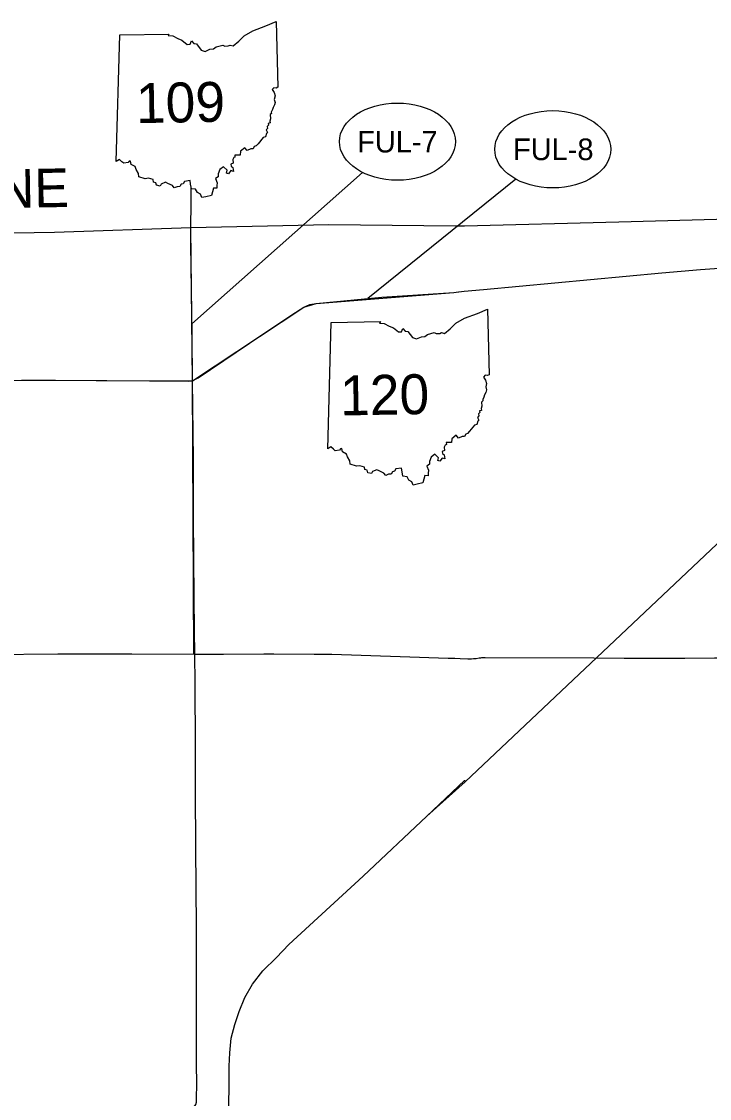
# Model space of a CAD drawing. Extents: x 0 to 849, y 0 to 440.
# Drawn here: x 399.3 to 488.2, y 214.9 to 354.2 of the extents above; entities that cross this region are included whole.
import ezdxf

# ---------------------------------------------------------------- set-up
doc = ezdxf.new("R2010")
doc.units = 0
for name, color, linetype in [('GM_X_Adjacent_County_Text', 7, 'Continuous'), ('GM_X_County', 7, 'Continuous'), ('GM_X_Interstate_Route', 7, 'Continuous'), ('PV_P_Walk', 7, 'Continuous'), ('RD_X_RR_2', 7, 'Continuous'), ('SH_Data', 7, 'Continuous')]:
    doc.layers.add(name, color=color, linetype=linetype)

msp = doc.modelspace()

# ---------------------------------------------------------------- linework, layer by layer
at = {"layer": 'GM_X_County'}
msp.add_lwpolyline([(390.27, 326.72), (403.53, 326.93), (421.18, 327.57), (438.99, 327.93), (455.38, 327.76), (456.49, 327.78), (456.55, 327.79), (476.51, 328.3), (493.89, 328.75), (511.84, 329.22), (529.24, 329.42), (538.61, 329.77), (546.79, 330.09), (564.28, 330.05), (564.46, 320.49), (564.74, 306.39), (564.89, 288.89), (565.03, 271.67), (565.17, 254.2), (565.19, 237.05), (565.2, 232.33), (565.21, 219.21), (565.34, 205.31)], dxfattribs=at)
at = {"layer": 'GM_X_Interstate_Route'}
for points in [[(421.67, 272.36), (421.64, 275.45), (421.61, 279.68), (421.51, 290.02), (421.49, 297.56), (421.36, 307.71), (421.35, 313.63), (421.17, 325.41), (421.22, 332.88)], [(458.99, 319.55), (482.08, 321.71), (487.07, 322.14), (491.86, 322.48), (493.95, 322.64), (496.53, 322.83), (502.87, 323.38), (507.37, 323.78), (509.49, 323.99), (509.55, 323.89), (509.68, 323.81), (510, 323.78), (510.29, 323.79)], [(421.36, 307.71), (421.86, 307.97), (422.13, 308.11), (428.77, 312.61), (434.21, 316.25), (435.77, 317.25), (436.54, 317.59), (437.37, 317.71), (439, 317.86), (455.18, 319.16), (455.79, 319.24), (455.8, 319.24)], [(455.8, 319.24), (456.5, 319.33), (458.99, 319.55)], [(392.29, 307.71), (392.29, 307.71), (394.11, 307.73), (395.71, 307.75), (395.96, 307.75), (399.29, 307.79), (399.29, 307.79)], [(399.29, 307.79), (400.51, 307.81)], [(400.51, 307.81), (400.86, 307.81), (403.66, 307.8), (408.93, 307.77), (415.82, 307.73), (420.8, 307.67), (421.36, 307.71)], [(326.28, 272.09), (332.98, 272.15), (340.32, 272.06), (344.27, 272.15), (346.61, 272.16), (351.08, 272.15), (358.34, 272.18), (366.67, 272.21), (368.5, 272.22), (377.41, 272.27), (385.4, 272.28), (390.75, 272.3), (391.52, 272.3), (395.11, 272.33), (403.95, 272.4), (411.47, 272.38), (412.84, 272.38), (413.53, 272.38)], [(413.53, 272.38), (421.67, 272.36)], [(421.67, 272.36), (425.4, 272.37), (430.59, 272.38), (431.9, 272.39), (437.13, 272.37), (439.41, 272.36), (448.21, 272.07), (454.45, 271.85), (454.56, 271.84)], [(421.89, 219.36), (421.9, 226.87), (421.89, 237.03), (421.83, 247.32), (421.76, 254.67), (421.75, 260.41), (421.71, 268.55), (421.67, 272.36)], [(454.56, 271.84), (455.28, 271.82), (455.97, 271.79), (456.98, 271.76), (457.04, 271.76), (457.46, 271.75), (457.72, 271.79), (457.99, 271.81)], [(457.99, 271.81), (458.07, 271.81), (458.45, 271.88), (458.66, 271.9), (458.81, 271.91), (459.24, 271.93), (473.29, 271.88)], [(473.29, 271.88), (477.19, 271.85), (485.05, 271.86), (488.86, 271.88), (490.09, 271.89), (493.69, 271.94), (498.86, 271.92), (498.96, 271.92), (504.03, 272.04), (507.8, 272.16), (507.87, 272.16), (510.81, 272.18), (511.47, 272.28), (512.4, 272.32), (516.54, 272.25), (518.32, 272.23), (523.68, 272.16), (527.6, 272.15), (528.32, 272.14)], [(419.15, 207.4), (419.18, 210.2), (419.2, 210.64), (419.29, 211.02), (419.53, 211.37), (421.58, 213.8), (421.8, 214.1), (421.91, 214.4), (421.9, 214.92), (421.92, 216.72), (421.89, 219.36)]]:
    msp.add_lwpolyline(points, dxfattribs=at)
at = {"layer": 'PV_P_Walk'}
for p, q in [((411.53, 336.1), (411.99, 352.48)), ((411.53, 336.1), (411.99, 352.48)), ((438.86, 298.91), (439.32, 315.28))]:
    msp.add_line(p, q, dxfattribs=at)
for points in [[(411.99, 352.48), (418.34, 352.58), (418.24, 352.39), (418.84, 352.34), (419.48, 351.99), (420.02, 351.77), (420.68, 351.25), (421.07, 351.26), (421.24, 351.69), (421.54, 351.36), (421.9, 351.3), (422.52, 350.51), (423.03, 350.34), (423.64, 350.61), (424.1, 350.66), (424.43, 350.92), (425.3, 351.15), (425.55, 351.01), (426.01, 351.04), (426.24, 351.14), (426.64, 351.05), (427.35, 351.65), (428.08, 352.35), (429.2, 353.01), (430.88, 353.64), (432.21, 354.2), (432.4, 345.7)], [(411.99, 352.48), (418.34, 352.58), (418.24, 352.39), (418.84, 352.34), (419.48, 351.99), (420.02, 351.77), (420.68, 351.25), (421.07, 351.26), (421.24, 351.69), (421.54, 351.36), (421.9, 351.3), (422.52, 350.51), (423.03, 350.34), (423.64, 350.61), (424.1, 350.66), (424.43, 350.92), (425.3, 351.15), (425.55, 351.01), (426.01, 351.04), (426.24, 351.14), (426.64, 351.05), (427.35, 351.65), (428.08, 352.35), (429.2, 353.01), (430.88, 353.64), (432.21, 354.2), (432.4, 345.7)], [(432.4, 345.7), (432.2, 345.58), (431.9, 345.64), (431.69, 345.4), (431.95, 345), (432.06, 344.58), (431.96, 344.12), (432.06, 343.74), (431.99, 343.42), (431.8, 343.1), (431.73, 342.8), (431.57, 342.48), (431.59, 342.3), (431.43, 342.16), (431.46, 341.63), (431.38, 341.33), (431.41, 341.08), (431.16, 341.01), (431.21, 340.8), (431.05, 340.64), (431.09, 340.36), (430.91, 340.18), (431.08, 339.83), (430.94, 339.71), (430.82, 339.28), (430.5, 339.19), (429.85, 338.4), (429.63, 338.1), (429.37, 338.02), (429.23, 337.72), (428.91, 337.72), (428.44, 337.5), (428.13, 337.87), (427.59, 337.43), (427.53, 336.92), (426.84, 336.93), (426.87, 336.67), (426.72, 336.6), (426.58, 336.34), (426.66, 335.88), (426.34, 335.76), (426.38, 335.5), (426.58, 335.33), (426.67, 334.82), (426.33, 334.93), (426.05, 334.5), (425.77, 334.6), (425.86, 334.96), (425.38, 335.4), (424.92, 335.05), (424.68, 334.49), (424.68, 334.11), (424.34, 333.89), (424.56, 333.35), (424.52, 332.99), (424.52, 332.64), (424.1, 332.65), (423.84, 331.71)], [(432.4, 345.7), (432.2, 345.58), (431.9, 345.64), (431.69, 345.4), (431.95, 345), (432.06, 344.58), (431.96, 344.12), (432.06, 343.74), (431.99, 343.42), (431.8, 343.1), (431.73, 342.8), (431.57, 342.48), (431.59, 342.3), (431.43, 342.16), (431.46, 341.63), (431.38, 341.33), (431.41, 341.08), (431.16, 341.01), (431.21, 340.8), (431.05, 340.64), (431.09, 340.36), (430.91, 340.18), (431.08, 339.83), (430.94, 339.71), (430.82, 339.28), (430.5, 339.19), (429.85, 338.4), (429.63, 338.1), (429.37, 338.02), (429.23, 337.72), (428.91, 337.72), (428.44, 337.5), (428.13, 337.87), (427.59, 337.43), (427.53, 336.92), (426.84, 336.93), (426.87, 336.67), (426.72, 336.6), (426.58, 336.34), (426.66, 335.88), (426.34, 335.76), (426.38, 335.5), (426.58, 335.33), (426.67, 334.82), (426.33, 334.93), (426.05, 334.5), (425.77, 334.6), (425.86, 334.96), (425.38, 335.4), (424.92, 335.05), (424.68, 334.49), (424.68, 334.11), (424.34, 333.89), (424.56, 333.35), (424.52, 332.99), (424.52, 332.64), (424.1, 332.65), (423.84, 331.71)], [(423.84, 331.71), (423.1, 331.53), (422.58, 331.42), (422.4, 331.85), (422.03, 332.07), (421.79, 332.5), (421.26, 332.56), (421.14, 333.15), (421.08, 333.63), (420.36, 333.51), (420.16, 333.22), (419.9, 333.14), (419.75, 332.85), (419.4, 332.82), (419.03, 332.68), (418.78, 332.97), (418.17, 333.26), (417.89, 333.41), (417.32, 333.18), (417.19, 332.91), (416.73, 333.03), (416.63, 333.33), (416.35, 333.43), (416.29, 333.75), (415.69, 333.93), (415.24, 333.86), (414.44, 334.12), (414.39, 334.55), (414.11, 335.07), (413.97, 335.43), (413.46, 335.71), (413.36, 336.14), (413.2, 336.13), (413.05, 335.96), (412.49, 335.88), (412.26, 336.05), (411.95, 336.35), (411.53, 336.1)], [(423.84, 331.71), (423.1, 331.53), (422.58, 331.42), (422.4, 331.85), (422.03, 332.07), (421.79, 332.5), (421.26, 332.56), (421.14, 333.15), (421.08, 333.63), (420.36, 333.51), (420.16, 333.22), (419.9, 333.14), (419.75, 332.85), (419.4, 332.82), (419.03, 332.68), (418.78, 332.97), (418.17, 333.26), (417.89, 333.41), (417.32, 333.18), (417.19, 332.91), (416.73, 333.03), (416.63, 333.33), (416.35, 333.43), (416.29, 333.75), (415.69, 333.93), (415.24, 333.86), (414.44, 334.12), (414.39, 334.55), (414.11, 335.07), (413.97, 335.43), (413.46, 335.71), (413.36, 336.14), (413.2, 336.13), (413.05, 335.96), (412.49, 335.88), (412.26, 336.05), (411.95, 336.35), (411.53, 336.1)], [(439.32, 315.28), (445.67, 315.39), (445.57, 315.19), (446.17, 315.15), (446.81, 314.8), (447.35, 314.58), (448, 314.06), (448.4, 314.07), (448.56, 314.49), (448.87, 314.16), (449.22, 314.1), (449.84, 313.32), (450.36, 313.15), (450.97, 313.42), (451.43, 313.46), (451.76, 313.73), (452.63, 313.96), (452.87, 313.82), (453.34, 313.85), (453.57, 313.95), (453.97, 313.86), (454.68, 314.45), (455.41, 315.16), (456.53, 315.82), (458.21, 316.45), (459.53, 317.01), (459.72, 308.51)], [(459.72, 308.51), (459.53, 308.39), (459.22, 308.45), (459.02, 308.21), (459.27, 307.81), (459.39, 307.39), (459.29, 306.93), (459.39, 306.55), (459.32, 306.23), (459.13, 305.91), (459.06, 305.6), (458.9, 305.29), (458.91, 305.11), (458.76, 304.97), (458.79, 304.43), (458.71, 304.14), (458.73, 303.89), (458.48, 303.82), (458.54, 303.61), (458.38, 303.45), (458.41, 303.17), (458.23, 302.99), (458.41, 302.63), (458.27, 302.52), (458.15, 302.09), (457.83, 302), (457.18, 301.21), (456.95, 300.91), (456.7, 300.83), (456.56, 300.52), (456.24, 300.52), (455.76, 300.31), (455.46, 300.68), (454.91, 300.23), (454.85, 299.72), (454.17, 299.74), (454.2, 299.48), (454.04, 299.41), (453.9, 299.15), (453.98, 298.69), (453.67, 298.57), (453.7, 298.3), (453.91, 298.14), (454, 297.63), (453.66, 297.73), (453.38, 297.31), (453.09, 297.41), (453.19, 297.77), (452.7, 298.21), (452.25, 297.86), (452.01, 297.3), (452.01, 296.92), (451.66, 296.69), (451.88, 296.16), (451.84, 295.79), (451.85, 295.44), (451.42, 295.46), (451.16, 294.52)], [(451.16, 294.52), (450.42, 294.34), (449.91, 294.23), (449.73, 294.66), (449.36, 294.88), (449.12, 295.31), (448.59, 295.37), (448.47, 295.96), (448.41, 296.44), (447.68, 296.32), (447.49, 296.03), (447.23, 295.95), (447.08, 295.65), (446.73, 295.63), (446.36, 295.49), (446.11, 295.78), (445.5, 296.07), (445.22, 296.22), (444.64, 295.99), (444.52, 295.71), (444.06, 295.83), (443.95, 296.14), (443.68, 296.23), (443.61, 296.56), (443.02, 296.73), (442.57, 296.66), (441.76, 296.93), (441.71, 297.36), (441.44, 297.88), (441.3, 298.24), (440.79, 298.52), (440.69, 298.95), (440.53, 298.94), (440.38, 298.76), (439.82, 298.68), (439.59, 298.86), (439.28, 299.16), (438.86, 298.91)]]:
    msp.add_lwpolyline(points, dxfattribs=at)
at = {"layer": 'RD_X_RR_2'}
for points in [[(456.64, 255.85), (519.4, 315.15)], [(425.79, 203.33), (426.05, 205.31), (426.17, 207.18), (426.03, 208.99), (426.13, 217.36), (426.11, 219.07), (426.19, 220.8), (426.39, 222.67), (426.87, 224.44), (427.42, 226.13), (428.13, 227.96), (429.14, 229.65), (430.47, 231.38), (432.22, 233.13), (433.83, 234.81), (443.44, 243.65), (451.69, 251.39), (456.64, 255.85)], [(425.97, 203.27), (426.05, 205.31), (426.17, 207.18), (426.03, 208.99), (426.13, 217.36), (426.11, 219.07), (426.19, 220.8), (426.39, 222.67), (426.87, 224.44), (427.42, 226.13), (428.13, 227.96), (429.14, 229.65), (430.47, 231.38), (432.22, 233.13), (433.83, 234.81), (443.44, 243.65), (451.69, 251.39), (456.57, 256), (456.64, 256)]]:
    msp.add_lwpolyline(points, dxfattribs=at)
at = {"layer": 'SH_Data'}
for p, q in [((443.37, 334.66), (421.3, 315.08)), ((463.19, 333.81), (444.07, 318.37)), ((399.29, 307.79), (421.36, 307.71))]:
    msp.add_line(p, q, dxfattribs=at)
for points in [[(421.57, 272.36), (421.36, 307.71), (421.18, 327.57)], [(421.36, 307.71), (435.77, 317.25), (437.37, 317.71), (445.87, 318.55), (455.18, 319.16)]]:
    msp.add_lwpolyline(points, dxfattribs=at)
for centre in [(447.88, 338.66), (467.96, 337.67)]:
    msp.add_ellipse(centre, major_axis=(7.5, 0), ratio=0.666667, dxfattribs=at)

# ---------------------------------------------------------------- texts
at = {"layer": 'GM_X_Adjacent_County_Text'}
msp.add_text('MICHIGAN STATE LINE', height=5.0058, rotation=1.0142, dxfattribs=at).set_placement((331.8, 328.91))
at = {"layer": 'PV_P_Walk'}
for s, p in [('109', (414.11, 341.05)), ('120', (440.51, 303.23))]:
    msp.add_text(s, height=5.162, rotation=1.0142, dxfattribs=at).set_placement(p)
at = {"layer": 'SH_Data'}
for s, p in [('FUL-7', (442.67, 337.26)), ('FUL-8', (462.83, 336.27))]:
    msp.add_text(s, height=2.8, dxfattribs=at).set_placement(p)

doc.saveas('drawing.dxf')
